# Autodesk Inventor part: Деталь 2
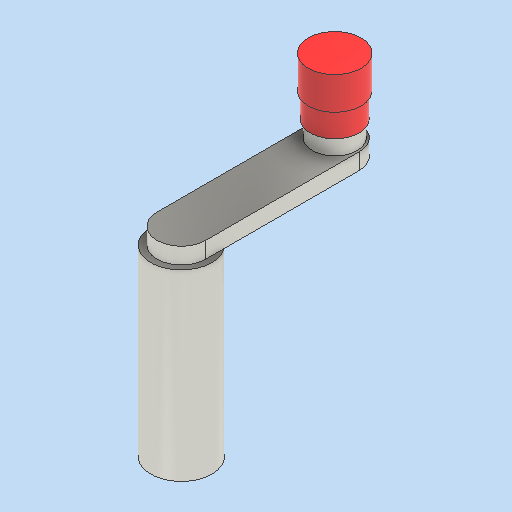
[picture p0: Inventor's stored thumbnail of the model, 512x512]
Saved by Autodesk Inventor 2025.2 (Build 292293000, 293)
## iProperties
Created: 2026-04
Part Number: Деталь 2
Material: Типовые
Document SubType Name: Modeling
Designer: igorr
Density: 1 g/cm^3
Appearance: По умолчанию
Author: igorr
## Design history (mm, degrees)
sketch "Эскиз1"
  geometry: C1 r 7.5 at (0, 0); 1 further point
  constraints: 1 centre point, 1 coincident
  dimensions: "d0" = 15 diameter of C1
extrude "Выдавливание1" new body sketch "Эскиз1" distance "d1" = 45; taper "d2" = 0 deg
sketch "Эскиз2"
  geometry: L1 (0, 0)-(0, 37.681); L2 (6, 0)-(6, 37.681); L3 (-6, 37.681)-(-6, 0); C1 r 6 at (0, 0); A1 r 6 centre (0, 0) between (-6, 0) and (6, 0); A2 r 6 centre (0, 37.681) between (6, 37.681) and (-6, 37.681); 4 further points
  constraints: 8 end point, 4 point on circle, 4 tangent, 3 centre point, 1 coincident, 1 concentric, 1 midpoint, 1 parallel, 1 vertical
  dimensions: "d3" = 12 diameter of C1; "d4" = 37.681 distance of L1.start L1.end
extrude "Выдавливание2" join sketch "Эскиз2" distance "d5" = 4; taper "d6" = 0 deg
sketch "Эскиз3"
  geometry: C1 r 5.5 at (0, 37.681); A1 r 6 centre (0, 37.681) between (6, 37.681) and (-6, 37.681) reference; 1 further point
  constraints: 1 centre point, 1 coincident
  dimensions: "d7" = 11 diameter of C1
extrude "Выдавливание3" join sketch "Эскиз3" distance "d8" = 4; taper "d9" = 0 deg
sketch "Эскиз4"
  geometry: C1 r 6 at (0, 0); A1 r 6 centre (0, 0) between (6, 0) and (-6, 0) reference; 3 further points
  constraints: 1 centre point, 1 coincident
extrude "Выдавливание4" join sketch "Эскиз4" distance "d10" = 14; taper "d11" = 0 deg
sketch "Эскиз5"
  geometry: C1 r 6.5 at (0, 0); A1 r 6 centre (0, 0) between (6, 0) and (-6, 0) reference; 1 further point
  constraints: 1 centre point, 1 coincident
  dimensions: "d12" = 13 diameter of C1
extrude "Выдавливание5" join sketch "Эскиз5" distance "d13" = 8; taper "d14" = 0 deg
node "Твердое тело1"
